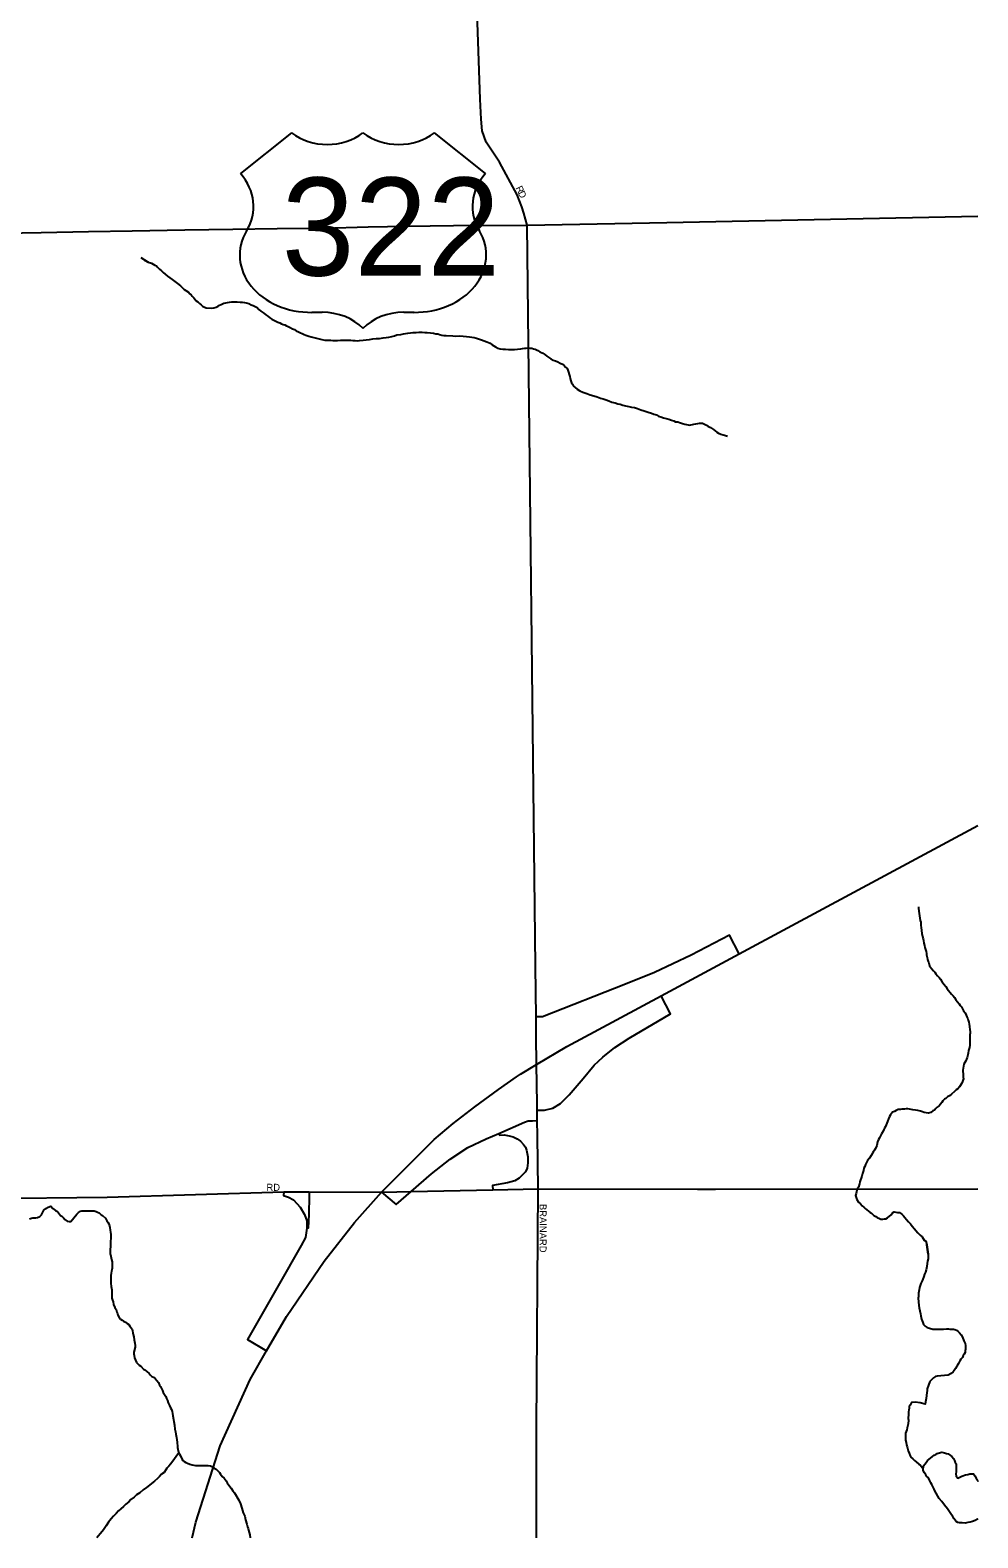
# Model space of a CAD drawing. Extents: x 2139079 to 2262683, y 1235796 to 1334992.
# Drawn here: x 2245377 to 2252112, y 1274636 to 1285350 of the extents above; entities that cross this region are included whole.
import ezdxf

# ---------------------------------------------------------------- set-up
doc = ezdxf.new("R2010")
doc.units = 0
for name, color, linetype in [('GM_X_City_Street', 7, 'Continuous'), ('GM_X_City_Street_Text', 7, 'Continuous'), ('GM_X_Interchange_Ramps', 7, 'Continuous'), ('GM_X_Interstate_Route', 7, 'Continuous'), ('GM_X_Minor_Lake', 7, 'Continuous'), ('GM_X_Minor_River', 7, 'Continuous'), ('GM_X_US_Location', 7, 'Continuous'), ('GM_X_US_Route', 7, 'Continuous'), ('GM_X_US_Shield', 7, 'Continuous')]:
    doc.layers.add(name, color=color, linetype=linetype)

msp = doc.modelspace()

# ---------------------------------------------------------------- linework, layer by layer
at = {"layer": 'GM_X_City_Street'}
for points in [[(2248908, 1283964), (2248885, 1284050), (2248872, 1284094), (2248839, 1284179), (2248713, 1284412), (2248617, 1284555), (2248589, 1284635), (2248581, 1284717), (2248574, 1284860), (2248556, 1285404), (2248530, 1287852)], [(2248968, 1278696), (2248908, 1283964)], [(2248974, 1278202), (2248972, 1278338), (2248968, 1278696)], [(2248976, 1278000), (2248974, 1278202)], [(2248979, 1277721), (2248976, 1278000)], [(2248982, 1277493), (2248981, 1277601), (2248980, 1277675), (2248979, 1277721)], [(2248986, 1277116), (2248982, 1277493)], [(2247882, 1277093), (2248085, 1277098), (2248664, 1277109), (2248986, 1277116)], [(2248975, 1274636), (2248976, 1275426), (2248986, 1277116)], [(2248986, 1277116), (2250119, 1277113)], [(2250119, 1277113), (2250248, 1277113), (2252112, 1277117)], [(2243300, 1277074), (2244429, 1277072), (2245061, 1277048), (2245925, 1277058), (2247179, 1277094), (2247360, 1277094), (2247873, 1277093), (2247882, 1277093)]]:
    msp.add_lwpolyline(points, dxfattribs=at)
at = {"layer": 'GM_X_Interchange_Ramps'}
for points in [[(2250416, 1278786), (2250346, 1278918), (2250075, 1278777), (2249813, 1278653), (2249608, 1278570), (2249019, 1278338), (2248972, 1278338)], [(2248980, 1277675), (2249032, 1277675), (2249091, 1277690), (2249146, 1277723), (2249208, 1277784), (2249306, 1277900), (2249386, 1277995), (2249447, 1278052), (2249532, 1278120), (2249635, 1278186), (2249927, 1278360), (2249861, 1278488)], [(2247873, 1277093), (2247977, 1277004), (2248085, 1277098), (2248230, 1277224), (2248361, 1277327), (2248488, 1277410), (2248618, 1277471), (2248708, 1277510), (2248889, 1277591), (2248917, 1277599), (2248948, 1277600), (2248981, 1277601)], [(2248708, 1277510), (2248713, 1277498), (2248745, 1277499), (2248781, 1277494), (2248810, 1277486), (2248838, 1277472), (2248862, 1277454), (2248884, 1277432), (2248896, 1277412), (2248904, 1277390), (2248914, 1277343), (2248914, 1277300), (2248910, 1277262), (2248896, 1277237), (2248873, 1277213), (2248851, 1277192), (2248822, 1277174), (2248770, 1277159), (2248663, 1277141), (2248664, 1277109)], [(2247179, 1277094), (2247178, 1277070), (2247213, 1277058), (2247248, 1277038), (2247296, 1276985), (2247327, 1276933), (2247342, 1276888), (2247343, 1276837), (2247333, 1276771), (2247303, 1276713), (2247140, 1276427), (2246921, 1276045), (2247057, 1275964)], [(2247360, 1277094), (2247360, 1277065), (2247357, 1276936), (2247352, 1276837), (2247343, 1276837)]]:
    msp.add_lwpolyline(points, dxfattribs=at)
at = {"layer": 'GM_X_Interstate_Route'}
msp.add_line((2250760, 1278971), (2252112, 1279697), dxfattribs=at)
for points in [[(2248841, 1277917), (2248862, 1277930), (2248976, 1278000), (2249191, 1278127), (2249415, 1278249), (2249861, 1278488), (2250416, 1278786), (2250760, 1278971)], [(2247911, 1277131), (2248249, 1277467), (2248383, 1277580), (2248537, 1277700), (2248706, 1277821), (2248834, 1277913), (2248841, 1277917)], [(2247873, 1277093), (2247911, 1277131)], [(2246529, 1274636), (2246553, 1274748), (2246728, 1275290), (2246941, 1275762), (2247057, 1275964), (2247198, 1276208), (2247466, 1276602), (2247682, 1276876), (2247873, 1277093)]]:
    msp.add_lwpolyline(points, dxfattribs=at)
at = {"layer": 'GM_X_Minor_Lake'}
for points in [[(2251726, 1275147), (2251735, 1275159), (2251745, 1275171), (2251755, 1275185), (2251775, 1275203), (2251789, 1275215), (2251801, 1275223), (2251813, 1275229), (2251823, 1275236), (2251847, 1275242), (2251857, 1275244), (2251875, 1275240), (2251889, 1275236), (2251901, 1275234), (2251917, 1275222), (2251928, 1275214), (2251938, 1275200), (2251946, 1275186), (2251952, 1275172), (2251958, 1275162), (2251958, 1275122), (2251957, 1275106), (2251955, 1275090), (2251959, 1275074), (2251971, 1275060), (2251985, 1275068), (2251999, 1275074), (2252025, 1275084), (2252041, 1275086), (2252055, 1275090), (2252081, 1275091), (2252091, 1275077), (2252100, 1275061), (2252110, 1275045), (2252112, 1275036)], [(2251807, 1274970), (2251801, 1274982), (2251793, 1275000), (2251785, 1275016), (2251779, 1275026), (2251772, 1275042), (2251762, 1275062), (2251748, 1275074), (2251742, 1275084), (2251732, 1275098), (2251724, 1275114), (2251726, 1275147)], [(2252112, 1274771), (2252110, 1274769), (2252092, 1274759), (2252074, 1274753), (2252058, 1274747), (2252040, 1274745), (2252022, 1274740), (2252000, 1274742), (2251982, 1274742), (2251970, 1274746), (2251958, 1274752), (2251941, 1274774), (2251935, 1274788), (2251925, 1274800), (2251915, 1274814), (2251897, 1274842), (2251876, 1274868), (2251856, 1274894), (2251838, 1274916), (2251807, 1274970)]]:
    msp.add_lwpolyline(points, dxfattribs=at)
at = {"layer": 'GM_X_Minor_River'}
for points in [[(2246163, 1283734), (2246216, 1283702), (2246189, 1283716), (2246216, 1283702), (2246238, 1283694), (2246252, 1283688), (2246262, 1283680), (2246274, 1283675), (2246282, 1283665), (2246296, 1283651), (2246311, 1283639), (2246323, 1283627), (2246337, 1283615), (2246353, 1283601), (2246369, 1283589), (2246385, 1283578), (2246404, 1283564), (2246424, 1283550), (2246446, 1283532), (2246460, 1283518), (2246472, 1283508), (2246484, 1283500), (2246501, 1283487), (2246511, 1283477), (2246521, 1283469), (2246529, 1283459), (2246539, 1283449), (2246557, 1283427), (2246569, 1283419), (2246580, 1283407), (2246592, 1283397), (2246602, 1283389), (2246612, 1283383), (2246628, 1283376), (2246668, 1283374), (2246682, 1283376), (2246698, 1283382), (2246712, 1283389), (2246722, 1283395), (2246734, 1283401), (2246744, 1283405), (2246754, 1283411), (2246768, 1283413), (2246780, 1283415), (2246794, 1283418), (2246810, 1283420), (2246830, 1283420), (2246848, 1283420), (2246870, 1283418), (2246886, 1283417), (2246900, 1283415), (2246912, 1283413), (2246930, 1283407), (2246948, 1283399), (2246962, 1283393), (2246975, 1283387), (2246989, 1283378), (2247001, 1283366), (2247017, 1283354), (2247037, 1283340), (2247051, 1283328), (2247065, 1283318), (2247080, 1283306), (2247094, 1283296), (2247108, 1283289), (2247122, 1283281), (2247136, 1283275), (2247150, 1283269), (2247162, 1283263), (2247174, 1283259), (2247186, 1283255), (2247198, 1283249), (2247211, 1283244), (2247225, 1283236), (2247241, 1283228), (2247255, 1283222), (2247267, 1283214), (2247283, 1283206), (2247297, 1283200), (2247311, 1283195), (2247325, 1283187), (2247337, 1283183), (2247358, 1283175), (2247374, 1283171), (2247430, 1283156), (2247450, 1283152), (2247470, 1283148), (2247486, 1283146), (2247502, 1283146), (2247514, 1283147), (2247528, 1283145), (2247542, 1283145), (2247562, 1283145), (2247582, 1283147), (2247600, 1283148), (2247614, 1283148), (2247630, 1283146), (2247644, 1283146), (2247656, 1283146), (2247670, 1283144), (2247686, 1283144)], [(2247686, 1283144), (2247701, 1283143), (2247717, 1283145), (2247743, 1283147), (2247765, 1283149), (2247789, 1283152), (2247813, 1283156), (2247835, 1283158), (2247859, 1283160), (2247885, 1283163), (2247907, 1283165), (2247925, 1283169), (2247947, 1283173), (2247965, 1283178), (2247983, 1283184), (2248011, 1283188), (2248029, 1283192), (2248045, 1283194), (2248061, 1283197), (2248079, 1283199), (2248097, 1283201), (2248119, 1283201), (2248141, 1283204), (2248163, 1283204), (2248181, 1283202), (2248199, 1283202), (2248223, 1283198), (2248243, 1283197), (2248259, 1283193), (2248273, 1283191), (2248287, 1283187), (2248303, 1283183), (2248317, 1283181), (2248333, 1283180), (2248381, 1283178), (2248401, 1283176), (2248431, 1283177), (2248455, 1283175), (2248478, 1283173), (2248498, 1283171), (2248516, 1283169), (2248532, 1283166), (2248548, 1283162), (2248564, 1283156), (2248584, 1283150), (2248604, 1283142), (2248622, 1283135), (2248646, 1283125), (2248661, 1283115), (2248673, 1283107), (2248685, 1283099), (2248701, 1283091), (2248717, 1283085), (2248735, 1283084), (2248755, 1283082), (2248777, 1283080), (2248797, 1283080), (2248819, 1283081), (2248841, 1283083), (2248863, 1283085), (2248877, 1283087), (2248889, 1283089), (2248901, 1283091), (2248915, 1283092), (2248929, 1283090), (2248941, 1283090), (2248953, 1283086), (2248967, 1283082), (2248984, 1283074), (2249000, 1283064), (2249020, 1283055), (2249034, 1283045), (2249048, 1283033), (2249062, 1283023), (2249078, 1283015), (2249094, 1283005), (2249111, 1282999), (2249127, 1282992), (2249143, 1282984), (2249159, 1282976), (2249171, 1282968), (2249181, 1282956), (2249193, 1282946), (2249199, 1282934), (2249212, 1282888), (2249214, 1282874), (2249220, 1282858), (2249225, 1282844), (2249231, 1282834), (2249239, 1282820), (2249249, 1282810), (2249265, 1282799), (2249283, 1282787), (2249305, 1282777), (2249332, 1282769), (2249356, 1282759), (2249382, 1282752), (2249406, 1282744), (2249430, 1282736), (2249450, 1282730), (2249470, 1282723)], [(2249470, 1282723), (2249490, 1282717), (2249511, 1282707), (2249535, 1282701), (2249553, 1282695), (2249571, 1282692), (2249589, 1282686), (2249609, 1282680), (2249631, 1282676), (2249651, 1282672), (2249671, 1282669), (2249693, 1282661), (2249716, 1282653), (2249740, 1282645), (2249770, 1282636), (2249792, 1282628), (2249810, 1282622), (2249828, 1282616), (2249842, 1282608), (2249860, 1282602), (2249878, 1282595), (2249897, 1282591), (2249915, 1282585), (2249935, 1282579), (2249951, 1282573), (2249963, 1282567), (2249981, 1282566), (2249991, 1282562), (2250013, 1282554), (2250029, 1282550), (2250041, 1282548), (2250053, 1282546), (2250063, 1282544), (2250093, 1282549), (2250107, 1282553), (2250121, 1282555), (2250133, 1282557), (2250143, 1282557), (2250155, 1282556), (2250173, 1282548), (2250184, 1282542), (2250194, 1282536), (2250212, 1282526), (2250234, 1282512), (2250244, 1282502), (2250258, 1282494), (2250270, 1282487), (2250286, 1282479), (2250301, 1282475), (2250311, 1282471), (2250325, 1282467), (2250333, 1282465)], [(2251690, 1279119), (2251691, 1279109), (2251695, 1279072), (2251699, 1279040), (2251703, 1279022), (2251706, 1279012), (2251708, 1279002), (2251708, 1278988), (2251710, 1278974), (2251712, 1278952), (2251715, 1278930), (2251719, 1278910), (2251723, 1278892), (2251725, 1278880), (2251729, 1278862), (2251733, 1278846), (2251736, 1278832), (2251740, 1278818), (2251744, 1278802), (2251746, 1278788), (2251748, 1278778), (2251752, 1278760), (2251755, 1278746), (2251759, 1278732), (2251763, 1278722), (2251769, 1278702), (2251783, 1278682), (2251798, 1278666), (2251806, 1278657), (2251814, 1278643), (2251826, 1278629), (2251838, 1278617), (2251846, 1278605), (2251857, 1278589), (2251873, 1278569), (2251885, 1278553), (2251895, 1278537), (2251926, 1278499), (2251936, 1278487), (2251946, 1278476), (2251956, 1278460), (2251968, 1278446), (2251979, 1278432), (2251987, 1278420), (2251995, 1278410), (2252003, 1278396), (2252011, 1278380), (2252021, 1278366), (2252028, 1278350), (2252034, 1278338), (2252040, 1278324), (2252044, 1278314), (2252048, 1278300), (2252050, 1278286), (2252052, 1278270), (2252055, 1278246), (2252057, 1278236), (2252057, 1278222), (2252055, 1278210), (2252055, 1278184), (2252056, 1278164), (2252056, 1278152), (2252054, 1278138), (2252052, 1278120), (2252046, 1278100), (2252043, 1278081), (2252041, 1278069), (2252035, 1278049), (2252027, 1278027), (2252019, 1278013), (2252013, 1278001), (2252010, 1277987), (2252008, 1277973), (2252006, 1277959), (2252008, 1277923), (2252008, 1277909), (2252009, 1277899), (2251999, 1277866), (2251981, 1277842), (2251969, 1277828), (2251959, 1277820), (2251947, 1277808), (2251926, 1277789), (2251910, 1277777), (2251896, 1277769), (2251884, 1277759), (2251874, 1277753), (2251864, 1277741), (2251856, 1277730), (2251846, 1277718), (2251836, 1277706), (2251824, 1277696), (2251813, 1277686), (2251803, 1277676), (2251793, 1277670), (2251777, 1277659), (2251761, 1277653), (2251745, 1277657), (2251731, 1277659), (2251719, 1277663), (2251705, 1277667)], [(2251705, 1277667), (2251685, 1277672), (2251668, 1277676), (2251650, 1277678), (2251614, 1277684), (2251602, 1277684), (2251590, 1277683), (2251572, 1277683), (2251562, 1277681), (2251546, 1277679), (2251532, 1277673), (2251520, 1277665), (2251506, 1277661), (2251491, 1277642), (2251483, 1277630), (2251477, 1277614), (2251469, 1277594), (2251465, 1277584), (2251461, 1277570), (2251455, 1277560), (2251449, 1277548), (2251444, 1277537), (2251438, 1277525), (2251428, 1277507), (2251420, 1277493), (2251412, 1277479), (2251406, 1277467), (2251400, 1277451), (2251393, 1277425), (2251385, 1277404), (2251377, 1277392), (2251371, 1277382), (2251363, 1277370), (2251353, 1277354), (2251342, 1277334), (2251328, 1277318), (2251320, 1277303), (2251314, 1277289), (2251308, 1277275), (2251302, 1277263), (2251299, 1277247), (2251293, 1277225), (2251287, 1277207), (2251273, 1277165), (2251270, 1277151), (2251264, 1277128), (2251256, 1277118), (2251252, 1277106), (2251248, 1277082), (2251242, 1277070), (2251253, 1277040), (2251265, 1277022), (2251277, 1277010), (2251291, 1276996), (2251302, 1276986), (2251312, 1276976), (2251322, 1276967), (2251336, 1276957), (2251346, 1276949), (2251356, 1276943), (2251374, 1276927), (2251386, 1276919), (2251396, 1276913), (2251413, 1276905), (2251423, 1276901), (2251437, 1276900), (2251449, 1276902), (2251459, 1276904), (2251469, 1276910), (2251496, 1276932), (2251506, 1276945), (2251518, 1276953), (2251530, 1276951), (2251542, 1276949), (2251556, 1276947), (2251571, 1276937), (2251583, 1276925), (2251593, 1276913), (2251605, 1276899), (2251619, 1276882), (2251633, 1276868), (2251646, 1276850), (2251662, 1276832), (2251672, 1276820), (2251686, 1276804), (2251702, 1276788), (2251717, 1276774), (2251731, 1276752), (2251743, 1276745), (2251750, 1276718)], [(2245372, 1276902), (2245386, 1276908), (2245396, 1276910), (2245408, 1276910), (2245418, 1276911), (2245428, 1276913), (2245446, 1276919), (2245458, 1276931), (2245466, 1276951), (2245474, 1276965), (2245488, 1276977), (2245505, 1276986), (2245523, 1276992), (2245538, 1276976), (2245556, 1276962), (2245570, 1276954), (2245592, 1276926), (2245602, 1276921), (2245614, 1276909), (2245623, 1276899), (2245639, 1276887), (2245655, 1276883), (2245665, 1276885), (2245708, 1276936), (2245720, 1276948), (2245734, 1276958)], [(2245734, 1276958), (2245744, 1276960), (2245754, 1276960), (2245766, 1276960), (2245784, 1276961), (2245796, 1276961), (2245810, 1276961), (2245832, 1276959), (2245846, 1276955), (2245856, 1276951), (2245867, 1276945), (2245881, 1276932), (2245891, 1276926), (2245911, 1276908), (2245921, 1276890), (2245929, 1276880), (2245936, 1276868), (2245940, 1276854), (2245942, 1276842), (2245946, 1276822), (2245948, 1276808), (2245950, 1276792), (2245949, 1276766), (2245947, 1276742), (2245946, 1276650)], [(2251760, 1276652), (2251750, 1276718), (2251760, 1276652), (2251760, 1276638), (2251758, 1276628), (2251758, 1276618), (2251755, 1276603), (2251753, 1276585), (2251749, 1276565), (2251745, 1276541), (2251739, 1276525), (2251733, 1276509), (2251729, 1276493), (2251722, 1276475), (2251716, 1276463), (2251708, 1276444), (2251702, 1276430), (2251698, 1276416), (2251694, 1276398), (2251690, 1276376), (2251691, 1276350), (2251689, 1276340), (2251693, 1276288), (2251695, 1276270), (2251699, 1276249), (2251704, 1276229), (2251708, 1276213), (2251710, 1276201), (2251712, 1276189), (2251716, 1276179), (2251720, 1276167), (2251726, 1276153), (2251737, 1276141), (2251751, 1276131), (2251769, 1276125), (2251793, 1276119), (2251823, 1276118), (2251847, 1276118), (2251869, 1276120), (2251889, 1276122), (2251903, 1276122), (2251913, 1276120), (2251927, 1276120), (2251938, 1276118), (2251948, 1276116), (2251960, 1276111), (2251972, 1276103), (2251982, 1276093), (2251994, 1276079), (2252004, 1276061), (2252013, 1276037), (2252021, 1276018), (2252025, 1276002), (2252025, 1275990), (2252025, 1275978), (2252023, 1275966), (2252021, 1275954), (2252015, 1275942), (2252007, 1275932), (2252002, 1275918), (2251992, 1275906), (2251984, 1275894), (2251974, 1275874), (2251962, 1275855), (2251954, 1275839), (2251944, 1275825), (2251936, 1275815), (2251922, 1275803), (2251900, 1275791), (2251848, 1275788), (2251824, 1275786), (2251812, 1275782), (2251796, 1275774), (2251784, 1275762), (2251772, 1275746), (2251762, 1275721), (2251753, 1275695), (2251751, 1275679), (2251749, 1275669), (2251747, 1275647), (2251745, 1275627), (2251741, 1275603), (2251737, 1275585), (2251703, 1275596), (2251667, 1275600), (2251641, 1275598), (2251631, 1275580), (2251625, 1275570), (2251623, 1275556), (2251621, 1275546), (2251619, 1275532), (2251620, 1275515), (2251618, 1275483), (2251620, 1275473), (2251618, 1275447), (2251614, 1275437), (2251610, 1275419), (2251607, 1275403), (2251603, 1275391), (2251599, 1275381)], [(2245947, 1276650), (2245954, 1276615), (2245960, 1276597), (2245960, 1276587), (2245960, 1276577), (2245960, 1276565), (2245960, 1276553), (2245956, 1276541), (2245954, 1276531), (2245952, 1276517), (2245951, 1276501), (2245949, 1276487), (2245949, 1276466), (2245951, 1276446), (2245953, 1276422), (2245956, 1276398), (2245958, 1276384), (2245958, 1276374), (2245958, 1276360), (2245958, 1276340), (2245962, 1276326), (2245966, 1276314), (2245970, 1276294), (2245979, 1276274), (2245987, 1276258), (2245993, 1276240), (2245997, 1276230), (2245999, 1276218), (2246009, 1276202), (2246018, 1276190), (2246030, 1276182), (2246040, 1276176), (2246054, 1276168), (2246066, 1276160), (2246078, 1276152), (2246086, 1276140), (2246094, 1276128), (2246101, 1276118), (2246105, 1276106), (2246107, 1276094), (2246109, 1276082), (2246113, 1276064), (2246117, 1276044), (2246120, 1276020), (2246122, 1276003), (2246122, 1275991), (2246114, 1275955), (2246114, 1275943), (2246116, 1275931), (2246118, 1275915), (2246125, 1275899), (2246133, 1275883), (2246141, 1275873), (2246151, 1275863), (2246163, 1275855), (2246183, 1275835), (2246196, 1275827), (2246206, 1275819), (2246222, 1275805), (2246230, 1275795), (2246242, 1275783), (2246254, 1275777), (2246264, 1275769), (2246276, 1275755), (2246289, 1275739), (2246297, 1275721), (2246303, 1275711), (2246311, 1275697), (2246317, 1275683), (2246323, 1275669), (2246332, 1275655), (2246340, 1275641), (2246346, 1275627), (2246352, 1275611), (2246358, 1275595), (2246366, 1275577), (2246375, 1275559), (2246381, 1275547), (2246385, 1275535), (2246389, 1275519), (2246391, 1275503), (2246402, 1275437), (2246406, 1275409), (2246410, 1275390), (2246412, 1275374), (2246415, 1275362), (2246417, 1275348), (2246419, 1275332), (2246421, 1275316), (2246421, 1275306), (2246423, 1275292), (2246425, 1275278), (2246427, 1275266), (2246432, 1275244), (2246438, 1275230), (2246444, 1275218), (2246454, 1275198), (2246462, 1275186), (2246472, 1275178), (2246482, 1275172)], [(2251599, 1275381), (2251597, 1275365), (2251599, 1275351), (2251599, 1275341), (2251599, 1275330), (2251603, 1275314), (2251606, 1275298), (2251610, 1275284), (2251612, 1275274), (2251618, 1275254), (2251624, 1275238), (2251632, 1275220), (2251636, 1275210), (2251649, 1275198), (2251663, 1275186), (2251673, 1275176), (2251693, 1275160), (2251703, 1275154), (2251724, 1275126)], [(2246433, 1275241), (2246384, 1275171), (2246374, 1275159), (2246362, 1275145), (2246348, 1275131), (2246340, 1275119), (2246328, 1275101), (2246311, 1275088), (2246297, 1275072), (2246281, 1275058), (2246261, 1275040), (2246203, 1274995), (2246179, 1274977), (2246155, 1274957), (2246133, 1274941), (2246115, 1274926), (2246093, 1274908), (2246077, 1274892), (2246057, 1274876), (2246040, 1274860), (2246022, 1274843), (2246004, 1274827), (2245988, 1274809), (2245970, 1274791), (2245952, 1274771), (2245934, 1274748), (2245916, 1274722), (2245898, 1274694), (2245877, 1274668), (2245861, 1274649), (2245851, 1274636)], [(2246482, 1275172), (2246495, 1275166), (2246511, 1275160), (2246529, 1275154), (2246551, 1275150), (2246567, 1275150), (2246579, 1275150), (2246595, 1275151), (2246607, 1275151), (2246625, 1275151), (2246641, 1275151), (2246659, 1275149), (2246673, 1275141), (2246684, 1275131), (2246698, 1275123), (2246708, 1275115), (2246722, 1275101), (2246730, 1275089), (2246742, 1275073), (2246755, 1275061), (2246763, 1275051), (2246769, 1275041), (2246777, 1275027), (2246789, 1275011), (2246805, 1274989), (2246818, 1274971), (2246830, 1274955), (2246860, 1274903), (2246871, 1274877), (2246881, 1274847), (2246891, 1274815), (2246902, 1274789), (2246908, 1274763), (2246916, 1274733), (2246922, 1274715), (2246926, 1274703), (2246929, 1274691), (2246933, 1274675), (2246937, 1274657), (2246941, 1274636)]]:
    msp.add_lwpolyline(points, dxfattribs=at)
at = {"layer": 'GM_X_US_Route'}
msp.add_line((2249901, 1283983), (2252112, 1284027), dxfattribs=at)
for points in [[(2243259, 1283849), (2243635, 1283859), (2244005, 1283871), (2244357, 1283879), (2244680, 1283890), (2244980, 1283899), (2245186, 1283907), (2245454, 1283913), (2245792, 1283919), (2246102, 1283924), (2246476, 1283930), (2246818, 1283936), (2247132, 1283941), (2247464, 1283944), (2247780, 1283952), (2248054, 1283956), (2248385, 1283962), (2248908, 1283964), (2249532, 1283976)], [(2249532, 1283976), (2249901, 1283983)]]:
    msp.add_lwpolyline(points, dxfattribs=at)
at = {"layer": 'GM_X_US_Shield'}
for p, q in [((2247234, 1284621), (2246872, 1284331)), ((2248612, 1284331), (2248250, 1284621)), ((2247379, 1283345), (2247452, 1283345)), ((2248032, 1283345), (2248105, 1283345))]:
    msp.add_line(p, q, dxfattribs=at)
for centre, major_axis, start_param, end_param in [((2247488, 1284828), (-363, 0), 0.795399, 2.346194), ((2247996, 1284828), (-363, 0), 0.795399, 2.346194), ((2246456, 1284098), (508, 0), 5.838949, 6.894067), ((2249028, 1284098), (-508, 0), 5.672304, 6.727422), ((2247374, 1283751), (508, 0), 2.702327, 4.723529), ((2248110, 1283751), (-508, 0), 1.559657, 3.580859), ((2247452, 1283055), (-363, 0), 3.785094, 4.712389), ((2248032, 1283055), (-363, 0), 4.712389, 5.639684)]:
    msp.add_ellipse(centre, major_axis=major_axis, ratio=0.8, start_param=start_param, end_param=end_param, dxfattribs=at)

# ---------------------------------------------------------------- texts
at = {"layer": 'GM_X_City_Street_Text'}
for s, rotation, p in [('R', 296.1849, (2248825, 1284229)), ('D', 294.3354, (2248842, 1284194)), ('RD', 0, (2247056, 1277102)), ('BRAINARD', 270, (2248997, 1277009))]:
    msp.add_text(s, height=50, rotation=rotation, dxfattribs=at).set_placement(p)
at = {"layer": 'GM_X_US_Location'}
for s in ['0', '/']:
    msp.add_text(s, height=1, dxfattribs=at).set_placement((2247743, 1283954))
msp.add_text('322', height=1, rotation=0, dxfattribs=at).set_placement((2247435, 1283747))
at = {"layer": 'GM_X_US_Shield'}
msp.add_text('322', height=696.1, dxfattribs=at).set_placement((2247164, 1283606))

doc.saveas('drawing.dxf')
